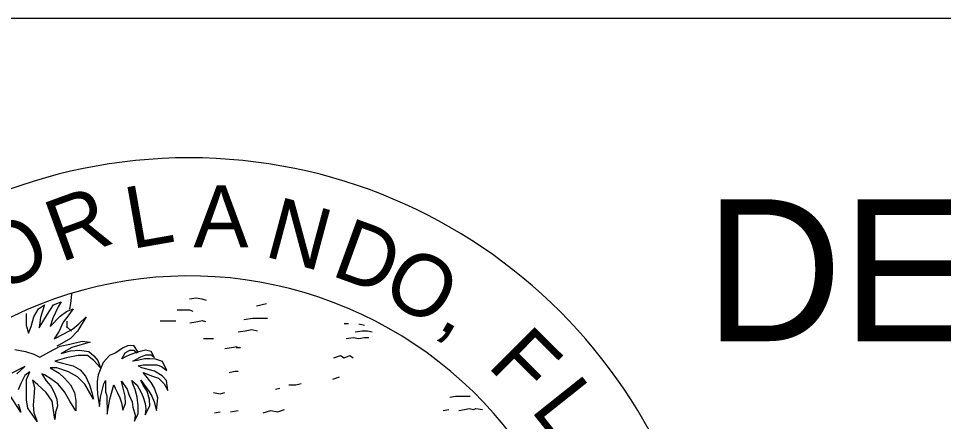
# Model space of a CAD drawing. Extents: x 2147138 to 2147698, y 2147153 to 2147515.
# Drawn here: x 2147568.66 to 2147592.33, y 2147199.7 to 2147210 of the extents above; entities that cross this region are included whole.
import ezdxf

# ---------------------------------------------------------------- set-up
doc = ezdxf.new("R2010")
doc.units = 0
doc.layers.add('BORDER', color=7, linetype='Continuous')
doc.layers.add('LEVEL_2', color=7, linetype='Continuous')

msp = doc.modelspace()

# ---------------------------------------------------------------- linework, layer by layer
at = {"layer": 'BORDER'}
for p, q in [((2147574.75, 2147202.657), (2147575.008, 2147202.713)), ((2147569.903, 2147202.266), (2147569.903, 2147202.094)), ((2147577.111, 2147202.195), (2147576.994, 2147202.195)), ((2147577.369, 2147202.195), (2147577.513, 2147202.166)), ((2147569.891, 2147202.129), (2147570.018, 2147202.012)), ((2147574.232, 2147201.59), (2147574.345, 2147201.59)), ((2147576.706, 2147200.783), (2147576.878, 2147200.842)), ((2147575.237, 2147200.525), (2147575.354, 2147200.554)), ((2147573.683, 2147199.92), (2147573.826, 2147199.949)), ((2147574.086, 2147199.949), (2147574.287, 2147199.978)), ((2147579.529, 2147199.978), (2147579.673, 2147200.006))]:
    msp.add_line(p, q, dxfattribs=at)
for points in [[(2147570.024, 2147202.966), (2147570, 2147202.783), (2147569.975, 2147202.603), (2147569.96, 2147202.565)], [(2147568.858, 2147202.46), (2147568.858, 2147202.16), (2147568.923, 2147201.959), (2147568.99, 2147202.126), (2147569.056, 2147202.377), (2147569.176, 2147202.579), (2147569.325, 2147202.679), (2147569.225, 2147202.361), (2147569.191, 2147202.094), (2147569.407, 2147202.444), (2147569.559, 2147202.679), (2147569.759, 2147202.763), (2147569.675, 2147202.628), (2147569.542, 2147202.343), (2147569.476, 2147202.126), (2147569.726, 2147202.395), (2147569.891, 2147202.512), (2147570.06, 2147202.579), (2147569.925, 2147202.395), (2147569.81, 2147202.244), (2147569.708, 2147202.009), (2147569.576, 2147201.811), (2147569.825, 2147201.943), (2147570.043, 2147202.06), (2147570.21, 2147202.195), (2147570.395, 2147202.377), (2147570.177, 2147202.009), (2147569.992, 2147201.826), (2147569.776, 2147201.692), (2147569.641, 2147201.626)], [(2147573.036, 2147202.834), (2147573.208, 2147202.862), (2147573.353, 2147202.834), (2147573.468, 2147202.805)], [(2147572.723, 2147202.553), (2147572.952, 2147202.553), (2147573.039, 2147202.553), (2147573.126, 2147202.524)], [(2147572.291, 2147202.272), (2147572.491, 2147202.272), (2147572.549, 2147202.272), (2147572.692, 2147202.272)], [(2147573.049, 2147202.225), (2147573.251, 2147202.253), (2147573.367, 2147202.282), (2147573.452, 2147202.253)], [(2147574.431, 2147202.308), (2147574.661, 2147202.339), (2147574.834, 2147202.339), (2147575.036, 2147202.339)], [(2147574.287, 2147201.993), (2147574.46, 2147202.022), (2147574.634, 2147202.05), (2147574.778, 2147202.022)], [(2147577.282, 2147201.993), (2147577.455, 2147202.022), (2147577.598, 2147202.022), (2147577.715, 2147201.993)], [(2147568.572, 2147201.541), (2147568.84, 2147201.492), (2147569.056, 2147201.424), (2147569.207, 2147201.342), (2147569.442, 2147201.476), (2147569.726, 2147201.626), (2147569.975, 2147201.676), (2147570.293, 2147201.758), (2147570.495, 2147201.726), (2147570.027, 2147201.593), (2147569.759, 2147201.442), (2147569.992, 2147201.507), (2147570.226, 2147201.525), (2147570.461, 2147201.492), (2147570.594, 2147201.376), (2147570.696, 2147201.258), (2147570.761, 2147201.074), (2147570.594, 2147201.258), (2147570.427, 2147201.389), (2147570.193, 2147201.389), (2147569.891, 2147201.324), (2147569.591, 2147201.241), (2147569.793, 2147201.191), (2147570.06, 2147201.124), (2147570.244, 2147201.025), (2147570.377, 2147200.857), (2147570.478, 2147200.64), (2147570.544, 2147200.439), (2147570.579, 2147200.272), (2147570.361, 2147200.657), (2147570.177, 2147200.839), (2147569.943, 2147200.974), (2147569.641, 2147201.074), (2147569.476, 2147201.074), (2147569.708, 2147200.94), (2147569.843, 2147200.807), (2147569.992, 2147200.64), (2147570.095, 2147200.439), (2147570.127, 2147200.238), (2147570.127, 2147199.971), (2147569.975, 2147200.222), (2147569.843, 2147200.456), (2147569.675, 2147200.657), (2147569.491, 2147200.792), (2147569.325, 2147200.891), (2147569.258, 2147200.923), (2147569.375, 2147200.74), (2147569.491, 2147200.606), (2147569.576, 2147200.439), (2147569.641, 2147200.272), (2147569.66, 2147200.089), (2147569.608, 2147199.938), (2147569.591, 2147199.753), (2147569.525, 2147200.222), (2147569.375, 2147200.439), (2147569.157, 2147200.64), (2147569.024, 2147200.757), (2147569.074, 2147200.572), (2147569.056, 2147200.322), (2147569.041, 2147200.122), (2147569.056, 2147199.92), (2147569.141, 2147199.703), (2147568.906, 2147200.038), (2147568.872, 2147200.255), (2147568.872, 2147200.54), (2147568.872, 2147200.774), (2147568.957, 2147200.974), (2147568.823, 2147200.874), (2147568.722, 2147200.674), (2147568.656, 2147200.507)], [(2147573.394, 2147201.82), (2147573.537, 2147201.82), (2147573.654, 2147201.82)], [(2147577.052, 2147201.82), (2147577.225, 2147201.849), (2147577.369, 2147201.82), (2147577.513, 2147201.849), (2147577.628, 2147201.849)], [(2147570.688, 2147200.392), (2147570.74, 2147200.08), (2147570.761, 2147200.321), (2147570.846, 2147200.661), (2147570.894, 2147200.745), (2147570.894, 2147200.661), (2147570.894, 2147200.564), (2147570.894, 2147200.455), (2147570.92, 2147200.357), (2147570.931, 2147199.884), (2147571.005, 2147200.272), (2147571.1, 2147200.636), (2147571.138, 2147200.551), (2147571.198, 2147200.431), (2147571.259, 2147200.308), (2147571.295, 2147200.175), (2147571.333, 2147199.992), (2147571.405, 2147200.163), (2147571.392, 2147200.345), (2147571.345, 2147200.551), (2147571.295, 2147200.734), (2147571.441, 2147200.527), (2147571.49, 2147200.392), (2147571.575, 2147200.201), (2147571.587, 2147200.066), (2147571.647, 2147199.859), (2147571.636, 2147199.713), (2147571.722, 2147199.908), (2147571.722, 2147200.103), (2147571.696, 2147200.321), (2147571.647, 2147200.515), (2147571.587, 2147200.661), (2147571.562, 2147200.745), (2147571.696, 2147200.626), (2147571.806, 2147200.443), (2147571.854, 2147200.321), (2147571.903, 2147200.163), (2147571.926, 2147200.028), (2147571.903, 2147199.872), (2147572.026, 2147200.103), (2147572.012, 2147200.261), (2147571.952, 2147200.48), (2147571.854, 2147200.626), (2147571.793, 2147200.758), (2147571.999, 2147200.48), (2147572.072, 2147200.345), (2147572.132, 2147200.201), (2147572.195, 2147199.981), (2147572.23, 2147200.308), (2147572.146, 2147200.551), (2147572.061, 2147200.697), (2147571.926, 2147200.867), (2147571.854, 2147200.951), (2147572.096, 2147200.856), (2147572.243, 2147200.805), (2147572.387, 2147200.661), (2147572.485, 2147200.49), (2147572.448, 2147200.745), (2147572.34, 2147200.867), (2147572.146, 2147200.989), (2147571.817, 2147201.074), (2147571.722, 2147201.122), (2147571.854, 2147201.146), (2147572.036, 2147201.146), (2147572.206, 2147201.146), (2147572.327, 2147201.109), (2147572.46, 2147201), (2147572.352, 2147201.23), (2147572.171, 2147201.291), (2147572.026, 2147201.304), (2147571.89, 2147201.304), (2147571.707, 2147201.256), (2147571.587, 2147201.245), (2147571.793, 2147201.352), (2147571.926, 2147201.401), (2147572.061, 2147201.401), (2147572.146, 2147201.329), (2147572.061, 2147201.487), (2147571.914, 2147201.522), (2147571.707, 2147201.475), (2147571.513, 2147201.401), (2147571.405, 2147201.352), (2147571.306, 2147201.304), (2147571.392, 2147201.46), (2147571.513, 2147201.522), (2147571.611, 2147201.522), (2147571.659, 2147201.475), (2147571.672, 2147201.46), (2147571.722, 2147201.475), (2147571.611, 2147201.644), (2147571.452, 2147201.632), (2147571.321, 2147201.571), (2147571.151, 2147201.46), (2147570.991, 2147201.389), (2147570.834, 2147201.207), (2147570.75, 2147201.025), (2147570.699, 2147200.891), (2147570.676, 2147200.721), (2147570.676, 2147200.576), (2147570.688, 2147200.392)], [(2147573.943, 2147201.563), (2147574.116, 2147201.59), (2147574.259, 2147201.619)], [(2147576.735, 2147201.33), (2147576.907, 2147201.389), (2147576.994, 2147201.33), (2147577.138, 2147201.389), (2147577.225, 2147201.33)], [(2147568.623, 2147200.923), (2147568.823, 2147201.107), (2147568.489, 2147200.94)], [(2147574.056, 2147200.956), (2147574.2, 2147200.985), (2147574.287, 2147200.985)], [(2147575.584, 2147200.64), (2147575.756, 2147200.64), (2147575.9, 2147200.669)], [(2147568.656, 2147200.155), (2147568.722, 2147199.938), (2147568.439, 2147200.372)], [(2147573.654, 2147200.438), (2147573.826, 2147200.409), (2147573.943, 2147200.438)], [(2147579.701, 2147200.323), (2147579.844, 2147200.351), (2147579.99, 2147200.351), (2147580.076, 2147200.351), (2147580.219, 2147200.351)], [(2147574.92, 2147199.92), (2147575.121, 2147199.978), (2147575.296, 2147199.949), (2147575.467, 2147200.006)], [(2147579.933, 2147199.978), (2147580.076, 2147200.006), (2147580.191, 2147200.036), (2147580.306, 2147200.006), (2147580.363, 2147200.036), (2147580.537, 2147200.006)]]:
    msp.add_lwpolyline(points, dxfattribs=at)
for radius, start, end in [(13.422, 0, 180), (10.402, 359.2052, 270.606)]:
    msp.add_arc((2147573.029, 2147193.02), radius, start, end, dxfattribs=at)
at = {"layer": 'LEVEL_2'}
msp.add_lwpolyline([(2147689.075, 2147210.003), (2147556.761, 2147210.003)], dxfattribs=at)

# ---------------------------------------------------------------- texts
at = {"layer": 'BORDER'}
for s, height, p in [('A', 1.581, (2147573.14, 2147204.154)), ('DEPARTMENT OF PUBLIC WORKS', 3.63, (2147586.232, 2147201.754))]:
    msp.add_text(s, height=height, dxfattribs=at).set_placement(p)
for s, rotation, p in [('R', 20, (2147569.738, 2147203.758)), ('L', 10, (2147571.556, 2147204.106)), ('N', 345, (2147574.915, 2147203.933)), ('O', 30, (2147568.182, 2147202.944)), ('D', 340, (2147576.625, 2147203.446)), ('O', 330, (2147577.882, 2147202.91)), (',', 330, (2147579.347, 2147202.123)), ('F', 315.1889, (2147580.632, 2147201.115)), ('L', 308.4769, (2147581.744, 2147200))]:
    msp.add_text(s, height=1.581, rotation=rotation, dxfattribs=at).set_placement(p)

doc.saveas('drawing.dxf')
